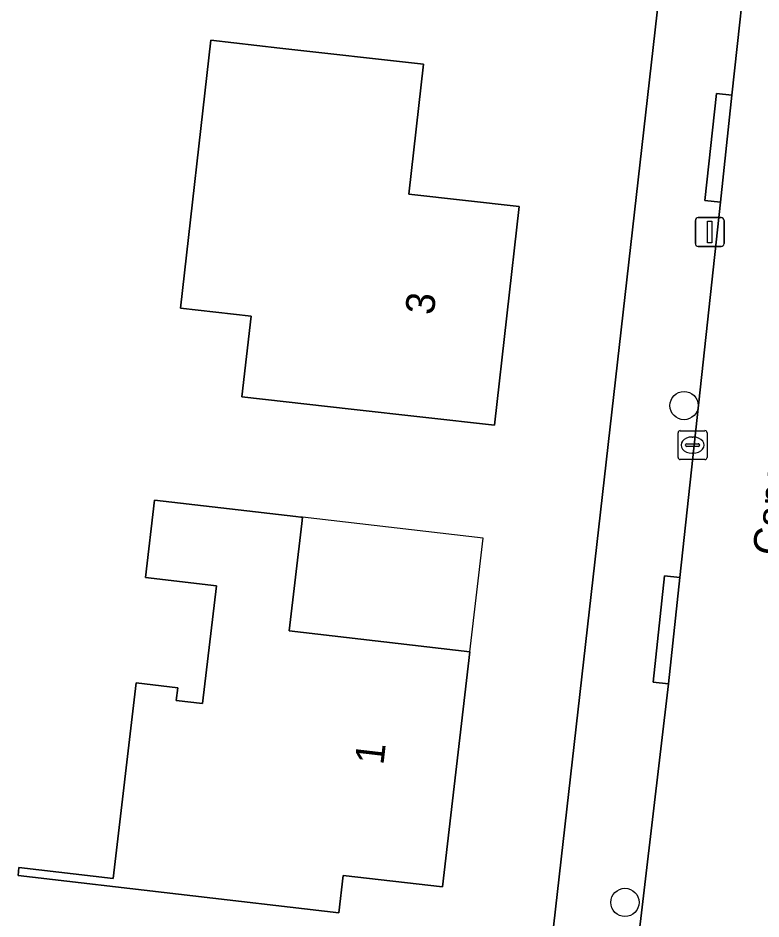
# Model space of a CAD drawing. Extents: x 162396 to 163643, y 386452 to 387406.
# Drawn here: x 162762.4 to 162788.12, y 386606.7 to 386637.89 of the extents above; entities that cross this region are included whole.
import ezdxf

# ---------------------------------------------------------------- set-up
doc = ezdxf.new("R2010")
doc.units = 0
for name, color, linetype in [('IMGEO_Boom', 7, 'Continuous'), ('IMGEO_Erf', 7, 'Continuous'), ('IMGEO_Kolk', 7, 'Continuous'), ('IMGEO_Lichtmast', 7, 'Continuous'), ('IMGEO_Openbare_ruimte_label', 7, 'Continuous'), ('IMGEO_Pand', 7, 'Continuous'), ('IMGEO_Pand_nummerreeks', 7, 'Continuous'), ('IMGEO_Pand_overbouw', 7, 'Continuous'), ('IMGEO_Rijbaan_lokaal_open', 7, 'Continuous'), ('IMGEO_Voetpad_open', 7, 'Continuous')]:
    doc.layers.add(name, color=color, linetype=linetype)

msp = doc.modelspace()

# ---------------------------------------------------------------- linework, layer by layer
at = {"layer": 'IMGEO_Boom'}
for centre in [(162785.458, 386624.47), (162783.413, 386607.271)]:
    msp.add_circle(centre, 0.489, dxfattribs=at)
at = {"layer": 'IMGEO_Erf'}
msp.add_lwpolyline([(162780.556, 386602.933), (162780.807, 386605.308), (162786.017, 386651.238)], dxfattribs=at)
for points in [[(162769.07, 386637.115), (162771.465, 386636.846), (162776.433, 386636.287), (162775.928, 386631.79), (162779.75, 386631.361), (162778.899, 386623.792), (162773.931, 386624.35), (162770.152, 386624.775), (162770.466, 386627.564), (162768.027, 386627.838)], [(162772.016, 386620.631), (162772.191, 386620.611), (162772.246, 386620.605), (162772.22, 386620.382), (162771.788, 386616.674), (162778.043, 386615.946), (162777.095, 386607.804), (162773.657, 386608.205), (162773.506, 386606.909), (162762.398, 386608.202), (162762.431, 386608.483), (162765.697, 386608.102), (162766.485, 386614.871), (162767.927, 386614.703), (162767.876, 386614.261), (162768.79, 386614.154), (162769.265, 386618.232), (162766.811, 386618.517), (162767.124, 386621.2)]]:
    msp.add_lwpolyline(points, close=True, dxfattribs=at)
at = {"layer": 'IMGEO_Kolk'}
for p, q in [((162785.253, 386622.675), (162785.253, 386623.527)), ((162785.328, 386623.601), (162786.18, 386623.601)), ((162785.741, 386623.381), (162785.766, 386623.381)), ((162786.254, 386623.527), (162786.254, 386622.675)), ((162785.512, 386623.095), (162785.512, 386623.107)), ((162785.95, 386623.058), (162785.552, 386623.058)), ((162785.555, 386623.144), (162785.953, 386623.144)), ((162785.996, 386623.107), (162785.996, 386623.095)), ((162785.764, 386622.821), (162785.739, 386622.821)), ((162786.18, 386622.601), (162785.328, 386622.601))]:
    msp.add_line(p, q, dxfattribs=at)
for points in [[(162785.253, 386622.675), (162785.253, 386623.527)], [(162785.328, 386623.601), (162786.18, 386623.601)], [(162786.254, 386623.527), (162786.254, 386622.675)], [(162786.18, 386622.601), (162785.328, 386622.601)]]:
    msp.add_lwpolyline(points, dxfattribs=at)
for centre, radius, start, end in [((162785.33, 386623.525), 0.0765, 91.552, 178.448), ((162785.33, 386623.525), 0.0765, 91.552, 178.448), ((162786.178, 386623.525), 0.0765, 1.552, 88.448), ((162786.178, 386623.525), 0.0765, 1.552, 88.448), ((162785.552, 386623.104), 0.0403, 85.8775, 175.7526), ((162785.549, 386623.094), 0.0366, 178.938, 274.7102), ((162785.953, 386623.101), 0.043, 264.8664, 352.4533), ((162785.957, 386623.106), 0.0386, 1.7309, 96.639), ((162785.33, 386622.677), 0.0765, 181.552, 268.448), ((162785.33, 386622.677), 0.0765, 181.552, 268.448), ((162786.178, 386622.677), 0.0765, 271.552, 358.448), ((162786.178, 386622.677), 0.0765, 271.552, 358.448)]:
    msp.add_arc(centre, radius, start, end, dxfattribs=at)
for centre, major_axis, ratio, start_param, end_param in [((162785.74, 386623.101), (-0.387, 0.002), 0.722429, 4.712389, 7.853982), ((162785.765, 386623.101), (-0.39, 0.002), 0.717154, 1.570796, 4.712389)]:
    msp.add_ellipse(centre, major_axis=major_axis, ratio=ratio, start_param=start_param, end_param=end_param, dxfattribs=at)
at = {"layer": 'IMGEO_Lichtmast'}
for p, q in [((162785.852, 386630.078), (162785.852, 386630.878)), ((162785.852, 386630.878), (162785.852, 386630.078)), ((162785.952, 386630.978), (162786.742, 386630.978)), ((162786.742, 386630.978), (162785.952, 386630.978)), ((162786.842, 386630.878), (162786.842, 386630.078)), ((162786.842, 386630.078), (162786.842, 386630.878)), ((162786.742, 386629.978), (162785.952, 386629.978)), ((162785.952, 386629.978), (162786.742, 386629.978))]:
    msp.add_line(p, q, dxfattribs=at)
msp.add_lwpolyline([(162786.272, 386630.853), (162786.422, 386630.853), (162786.422, 386630.103), (162786.272, 386630.103), (162786.272, 386630.853)], dxfattribs=at)
for centre, start, end in [((162785.952, 386630.878), 90, 180), ((162785.952, 386630.878), 90, 180), ((162786.742, 386630.878), 0, 90), ((162786.742, 386630.878), 360, 90), ((162785.952, 386630.078), 180, 270), ((162785.952, 386630.078), 180, 270), ((162786.742, 386630.078), 270, 0), ((162786.742, 386630.078), 270, 0)]:
    msp.add_arc(centre, 0.1, start, end, dxfattribs=at)
at = {"layer": 'IMGEO_Pand'}
for points in [[(162769.07, 386637.115), (162768.027, 386627.838), (162770.466, 386627.564), (162770.152, 386624.775), (162773.931, 386624.35), (162778.899, 386623.792), (162779.75, 386631.361), (162775.928, 386631.79), (162776.433, 386636.287), (162771.465, 386636.846)], [(162778.043, 386615.946), (162771.788, 386616.674), (162772.22, 386620.382), (162772.246, 386620.605), (162772.191, 386620.611), (162772.016, 386620.631), (162767.124, 386621.2), (162766.811, 386618.517), (162769.265, 386618.232), (162768.79, 386614.154), (162767.876, 386614.261), (162767.927, 386614.703), (162766.485, 386614.871), (162765.697, 386608.102), (162762.431, 386608.483), (162762.398, 386608.202), (162773.506, 386606.909), (162773.657, 386608.205), (162777.095, 386607.804)]]:
    msp.add_lwpolyline(points, close=True, dxfattribs=at)
at = {"layer": 'IMGEO_Pand_overbouw'}
msp.add_lwpolyline([(162778.501, 386619.876), (162772.246, 386620.605), (162772.22, 386620.382), (162771.788, 386616.674), (162778.043, 386615.946)], close=True, dxfattribs=at)
at = {"layer": 'IMGEO_Rijbaan_lokaal_open'}
msp.add_lwpolyline([(162788.796, 386650.757), (162787.792, 386641.469), (162787.39, 386637.74), (162787.117, 386635.214), (162786.717, 386631.512), (162785.313, 386618.521), (162784.915, 386614.835), (162783.817, 386605.445), (162783.558, 386603.229)], dxfattribs=at)
at = {"layer": 'IMGEO_Voetpad_open'}
for points in [[(162855.09, 386662.415), (162787.296, 386663.004), (162786.017, 386651.238), (162780.807, 386605.308), (162780.556, 386602.933)], [(162786.717, 386631.512), (162786.177, 386631.573), (162786.586, 386635.274), (162787.117, 386635.214), (162787.39, 386637.74), (162787.792, 386641.469), (162788.796, 386650.757)], [(162783.558, 386603.229), (162783.817, 386605.445), (162784.915, 386614.835), (162784.387, 386614.892), (162784.776, 386618.579), (162785.313, 386618.521), (162786.717, 386631.512)]]:
    msp.add_lwpolyline(points, dxfattribs=at)
for points in [[(162787.117, 386635.214), (162786.586, 386635.274), (162786.177, 386631.573), (162786.717, 386631.512)], [(162785.313, 386618.521), (162784.776, 386618.579), (162784.387, 386614.892), (162784.915, 386614.835)]]:
    msp.add_lwpolyline(points, close=True, dxfattribs=at)

# ---------------------------------------------------------------- texts
at = {"layer": 'IMGEO_Openbare_ruimte_label'}
msp.add_text('Canopuslaan', height=1, rotation=83.6851, dxfattribs=at).set_placement((162788.822, 386619.244))
at = {"layer": 'IMGEO_Pand_nummerreeks'}
for s, rotation, p in [('3', 83.585, (162776.79, 386627.585)), ('1', 83.3596, (162775.047, 386612.005))]:
    msp.add_text(s, height=1, rotation=rotation, dxfattribs=at).set_placement(p)

doc.saveas('drawing.dxf')
